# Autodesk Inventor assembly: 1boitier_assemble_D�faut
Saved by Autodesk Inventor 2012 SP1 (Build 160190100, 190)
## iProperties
Created: 2011-01
Part Number: 1boitier_assemble_D�faut
Document SubType Name: Assembly
Designer: eric
Mass: 73.238 g
Surface Area: 581.356 cm^2
Volume: 73.238 cm^3
Density: 1 g/cm^3
Author: eric
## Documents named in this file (10)
- D:\Cours\Inventor salle SI\chariot_de_golf_2008\chariot_de_golf_trolem\1boitier_assemble_Defaut.iam
- D:\Cours\Inventor salle SI\chariot_de_golf_2008\chariot_de_golf_trolem\1fond_boitier_Defaut.ipt
- D:\Cours\Inventor salle SI\chariot_de_golf_2008\chariot_de_golf_trolem\bead2_Defaut.ipt
- D:\Cours\Inventor salle SI\chariot_de_golf_2008\chariot_de_golf_trolem\46Vis CBLZ M5-10.ipt
- D:\Cours\Inventor salle SI\chariot_de_golf_2008\chariot_de_golf_trolem\1boitier_Defaut.ipt
- D:\Cours\Inventor salle SI\chariot_de_golf_2008\chariot_de_golf_trolem\bead19_Defaut.ipt
- D:\Cours\Inventor salle SI\chariot_de_golf_2008\chariot_de_golf_trolem\1plaque_arriere_boitier_Defaut.ipt
- D:\Cours\Inventor salle SI\chariot_de_golf_2008\chariot_de_golf_trolem\bead9_Defaut.ipt
- D:\Cours\Inventor salle SI\chariot_de_golf_2008\chariot_de_golf_trolem\bead1_Defaut.ipt
- D:\Cours\Inventor salle SI\chariot_de_golf_2008\chariot_de_golf_trolem\1plaque_avant_boitier_Defaut.ipt
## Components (11 placed, 9 different names)
1. 1fond_boitier_Defaut:1
2. bead2_Defaut:1
3. 46Vis CBLZ M5-10:1
4. 1boitier_Defaut:1
5. bead19_Defaut:1
6. 46Vis CBLZ M5-10:2
7. 1plaque_arriere_boitier_Defaut:1
8. bead9_Defaut:1
9. bead1_Defaut:1
10. 46Vis CBLZ M5-10:3
11. 1plaque_avant_boitier_Defaut:1
